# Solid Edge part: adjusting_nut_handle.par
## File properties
Title: Adjusting nut handle
Author: Deepak Maini
Template: Normal.par
Last saved by: Robert a Rhodes jr
Revision: 4
Application: Solid Edge
Material: aluminum
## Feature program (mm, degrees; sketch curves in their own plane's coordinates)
sketch for "unnamed Protrusion 1" plane through (0, 0, 0) normal (0, -1, 0) x-axis (1, 0, 0)
  circle centre (0, 0) radius 9.5123
extrude "unnamed Protrusion 1" add finite 127 symmetric
chamfer "unnamed Chamfer 1"
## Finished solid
Body 1: solid body, 5 faces, 4 edges, 0 vertices.
  Faces by surface: cone 2, plane 2, cylinder 1
  Edges by curve: circle 4
Bounding box of the edges (mm): 19.025 x 127.000 x 19.025, from (-9.5123, -63.5, -9.5123) to (9.5123, 63.5, 9.5123).
Cylindrical faces by radius (mm): R9.5123 x1
Conical faces (half-angle, radius in mm at the cone's reference point): 45 deg R7.9375 x1, 45 deg R9.5123 x1
Planar faces by outward normal: +y 1, -y 1
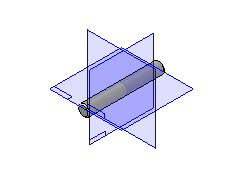
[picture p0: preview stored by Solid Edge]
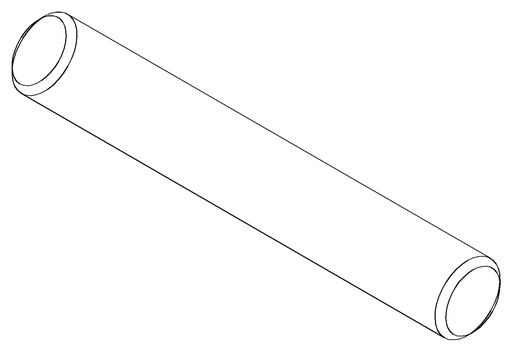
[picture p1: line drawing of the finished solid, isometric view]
